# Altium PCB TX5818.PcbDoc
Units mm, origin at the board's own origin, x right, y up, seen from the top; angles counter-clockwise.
Board outline 55.26 x 55.25 mm, 2 copper layers (TopLayer, BottomLayer); 37 components, 34 nets, 107 pads, 481 vias.
Unrouted connection lines stored in the file: 3.
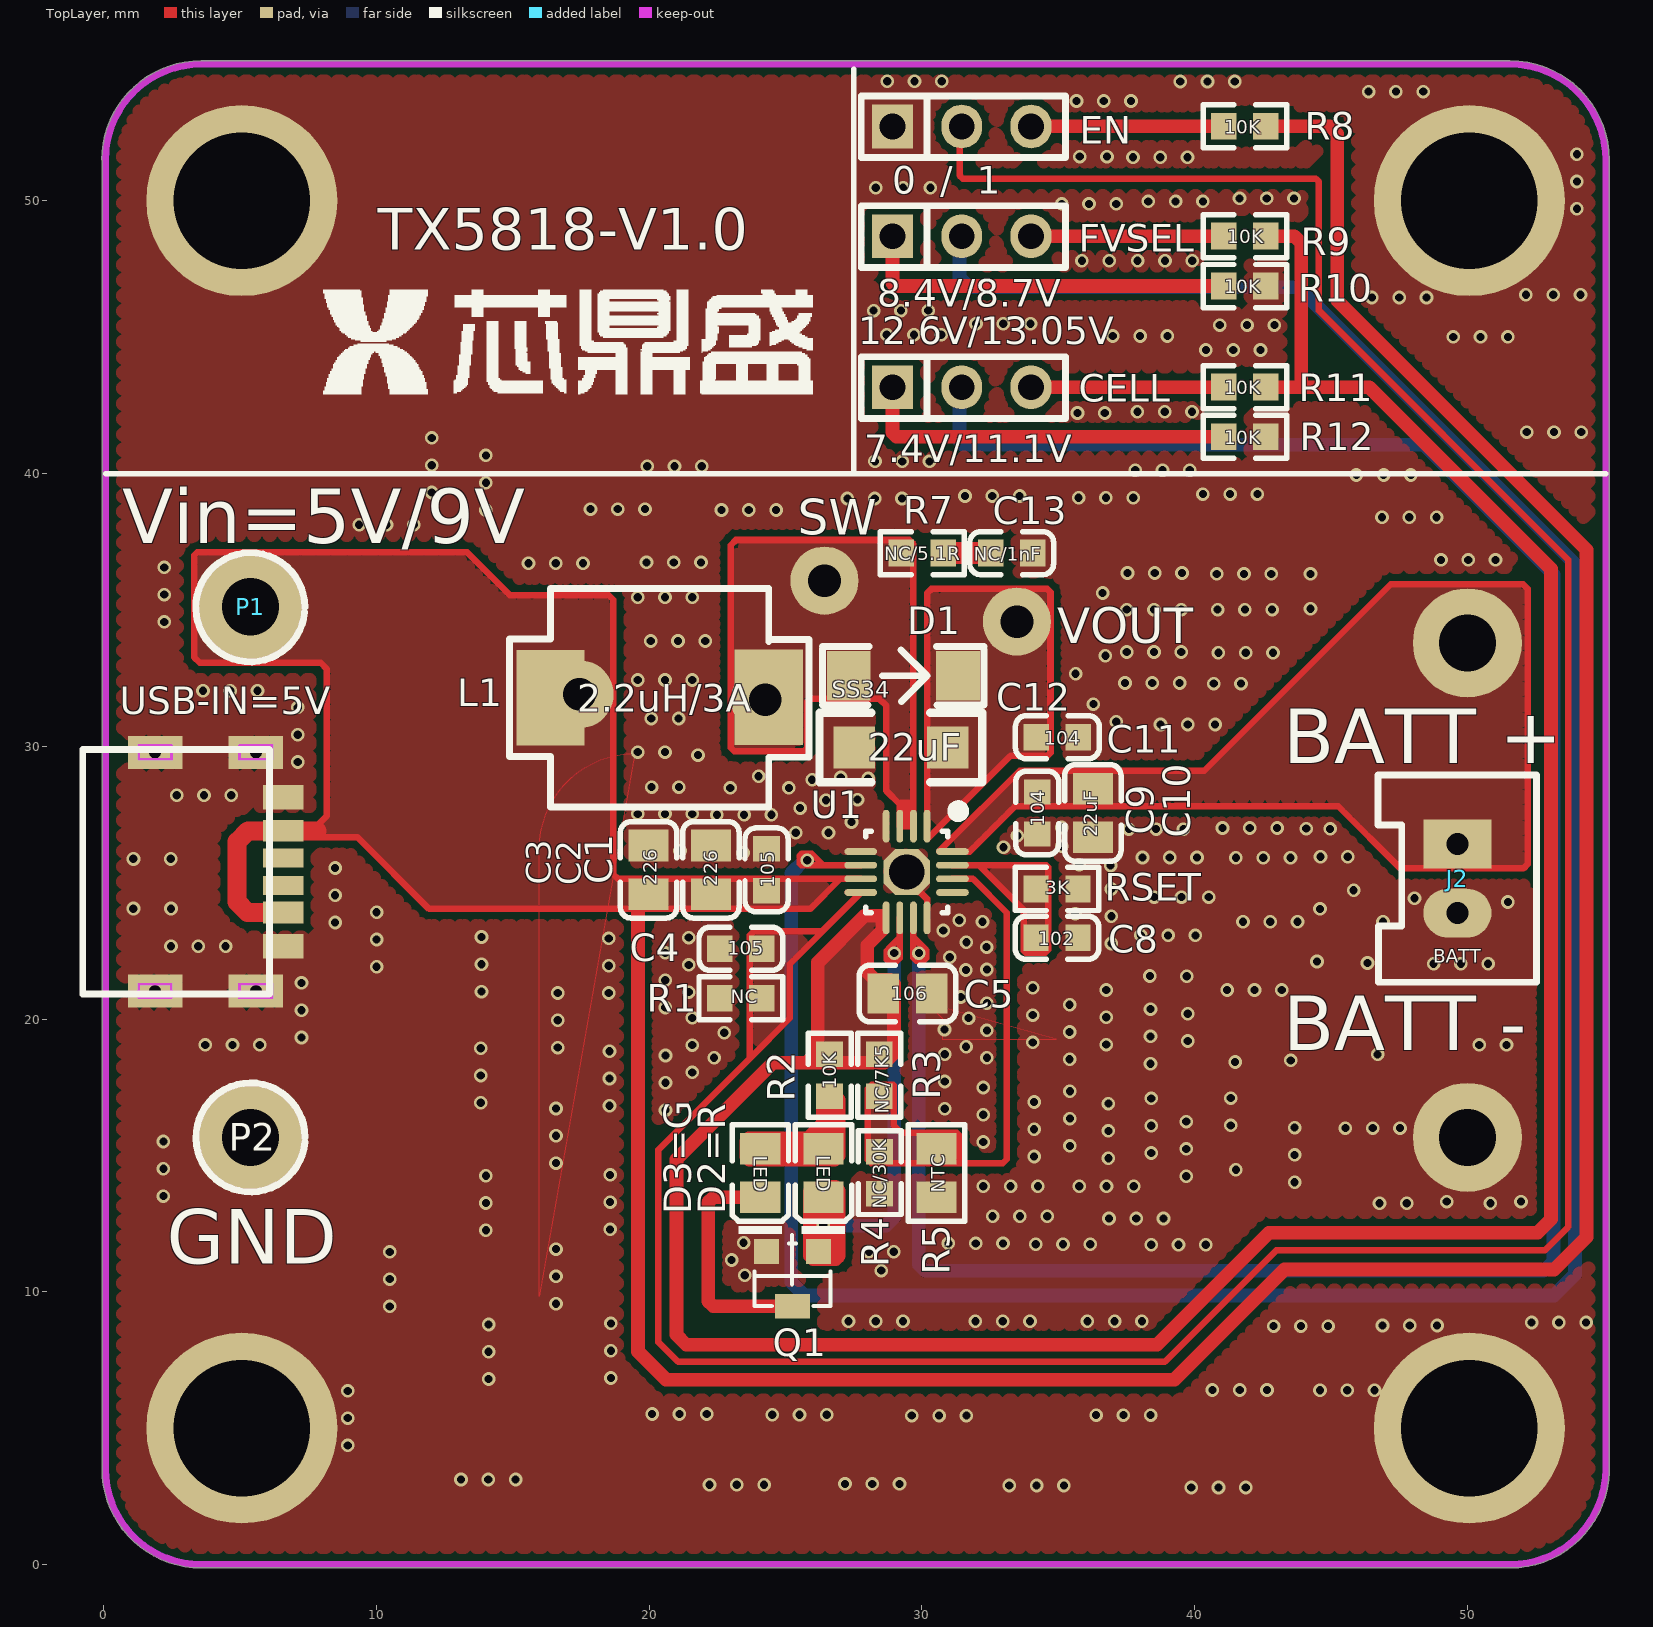
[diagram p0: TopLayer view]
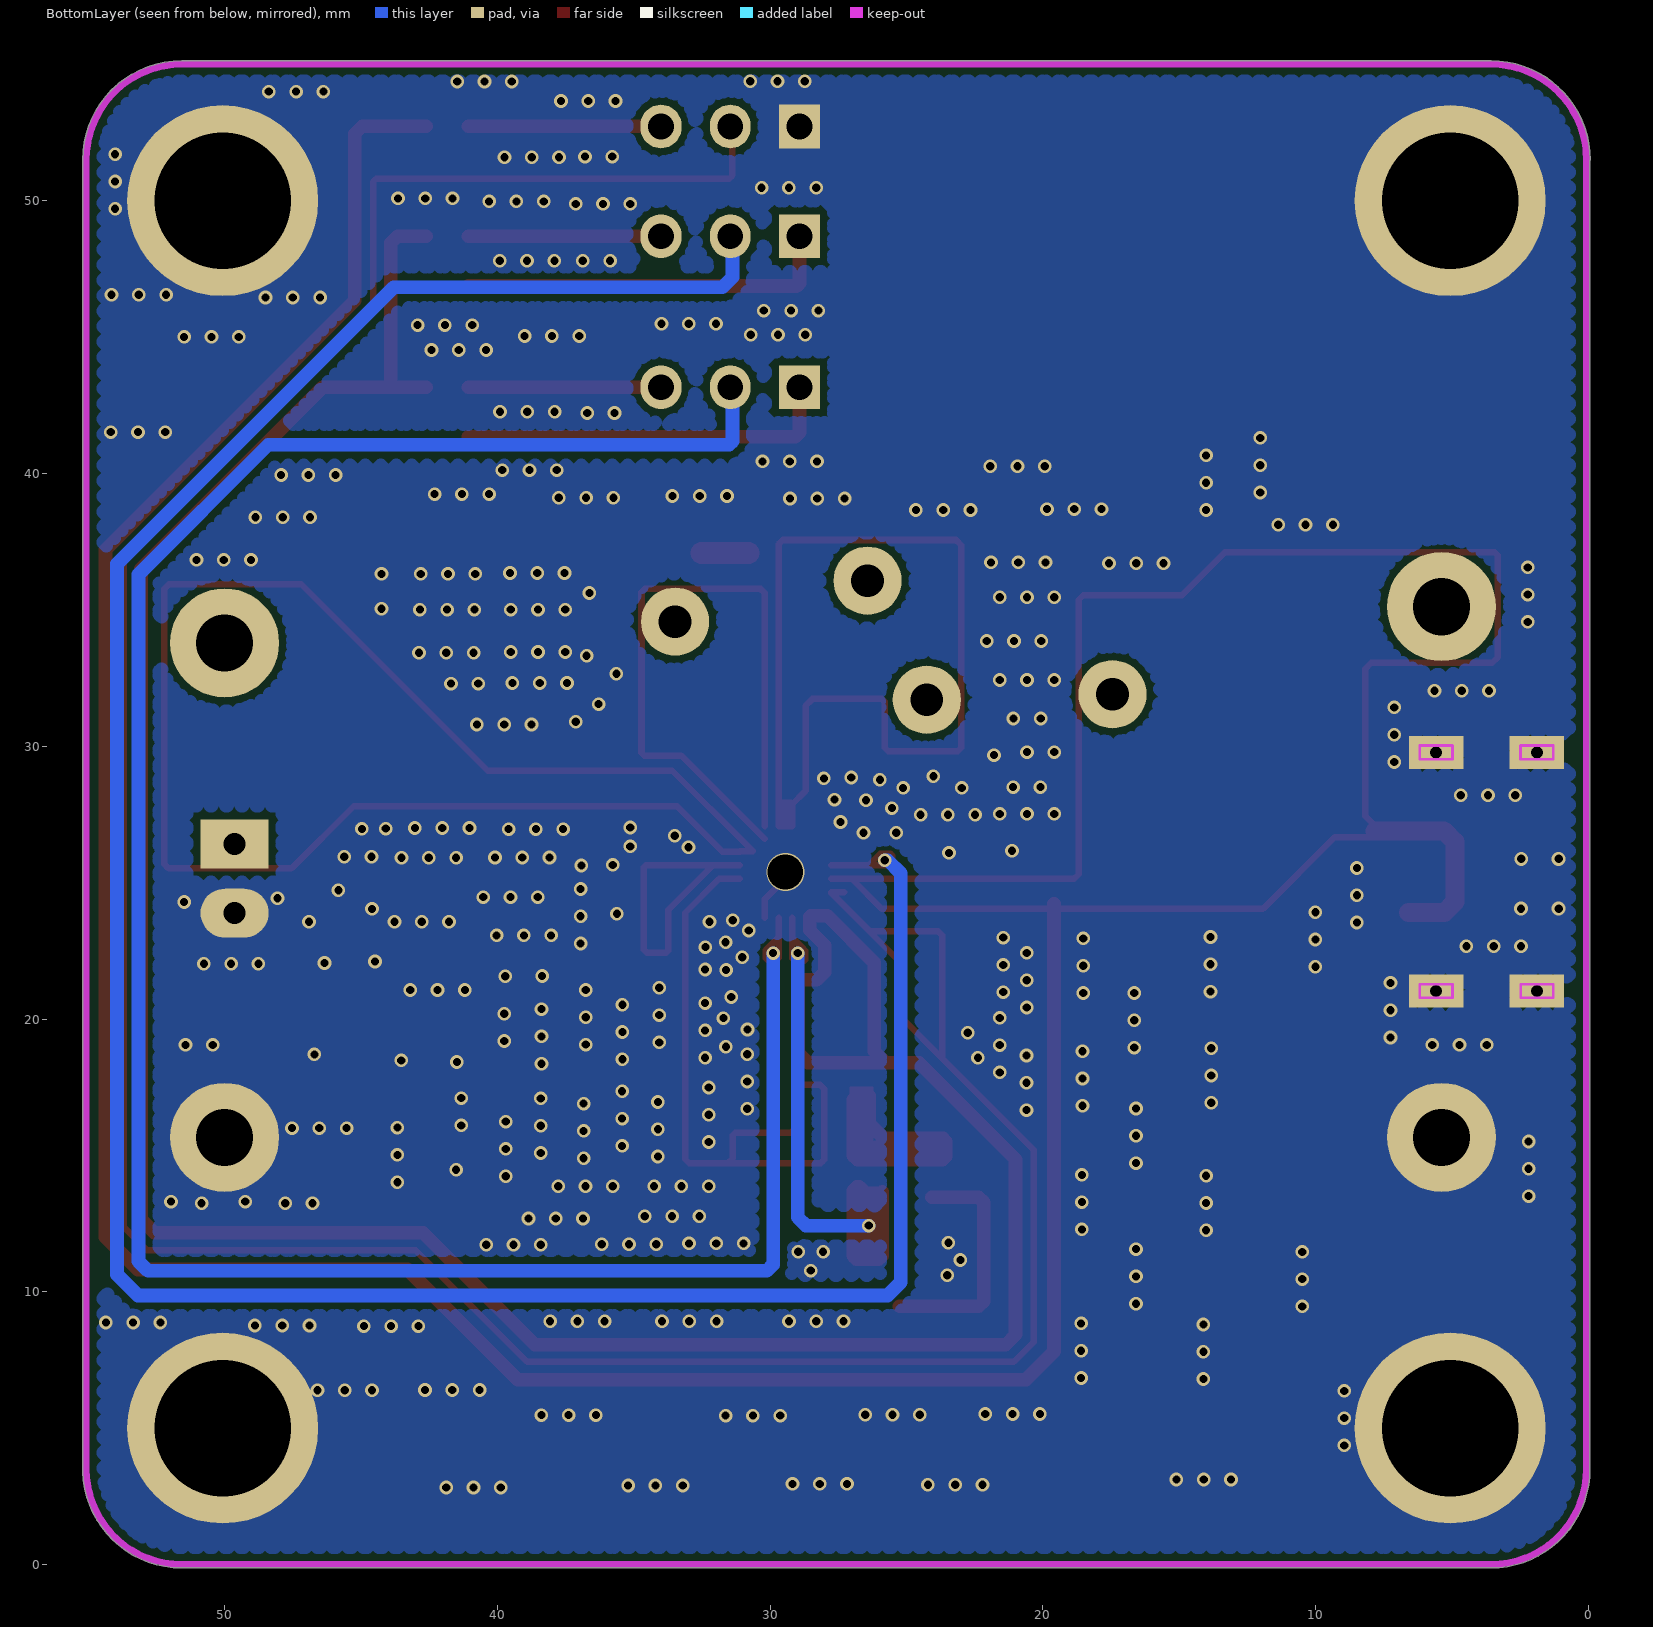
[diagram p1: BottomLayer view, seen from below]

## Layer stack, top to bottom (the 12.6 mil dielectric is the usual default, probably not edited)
TopLayer: signal copper 0.0356
Dielectric: dielectric 0.32, FR-4, Dk 4.8
BottomLayer: signal copper 0.0356

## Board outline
-0.057,3.51 -0.057,46.299 cw(c0.07,46.306) -0.057,46.306 -0.057,51.479 cw(c0.066,51.51) -0.061,51.51 cw(c3.566,51.51) 3.566,55.137 cw(c3.566,55.01) 3.567,55.137 51.572,55.137 cw(c51.572,51.51) 55.199,51.51 cw(c55.072,51.51) 55.199,51.51 55.198,3.527 cw(c55.072,3.51) 55.199,3.51 cw(c51.572,3.51) 55.198,3.416 55.198,3.414 cw(c55.07,3.414) 55.197,3.405 cw(c51.572,3.51) 51.572,-0.118 3.57,-0.118 cw(c3.57,3.51)

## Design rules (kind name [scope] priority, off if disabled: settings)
Clearance [All] p1: gap=0.254
PolygonConnect [All] p1: connectstyle=Direct reliefconductorwidth=0.254 reliefentries=4 polygonreliefangle="90 Angle"
RoutingVias [All] p1: holewidth=0.381 width=0.432 viastyle="Through Hole" minholewidth=0.381 minwidth=0.432 maxholewidth=0.381 maxwidth=0.432
SilkscreenOverComponentPads SilkToSolderMaskClearance [IsPad] p1: minsilkscreentomaskgap=0.254
SolderMaskExpansion [All] p1: expansion=0.102
TestPointUsage [All] p1: valid=0 allowmultiple=FALSE
Testpoint [All] p1: side=3 testpointundercomponent=TRUE minsize=1.016 maxsize=2.54 preferedsize=1.524 minholesize=0.508 maxholesize=1.016 preferedholesize=0.813 testpointgrid=0.025 style=297 order=0-112345678
Width [All] p1: maxlimit=5.08 minlimit=0.15 preferedwidth=0.24
23 further rules are at their usual default settings.

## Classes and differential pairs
component class NS4296_DEMO_V1: C2 C8 C12 C18 C34 C37 C38 C39 C40 J3 J4 J5 J6 J7 J9 J10 LS1 LS2 LS3 R4 R6 R10 RSET S2 S3 USB-IN=5V
component class PA: C12 C15 C16 C17 C18 C19 C20 C26 C34 C35 C36 C40 C62 C66 Cc Ci+ Ci- Cp J9 Jin LS3 R0/nc R6 R8 R19 R46 Rc2 Rf Rg Ro- U3 U8 U9 Uic
component class NS4358_2: C12 C15 C16 C17 C18 C19 C20 C26 C30 C34 C35 C36 C40 Cc Cg Ci+ Ci- Cp J5 J9 Jin Jp LS3 R0/nc R6 R8 R19 Rc2 Rf Rg Ro- Uic
component class NS4158_DEMO: C2 Cb Cc Cg Ci+ Ci- Cp Cv Jin Jp LSo R0/nc Rc1 Rc2 Rf Rg Ri+ Ri- Sc Uic Xi Xig Xo+ Xo- Xv+ Xv-
component class ANT2801DEMO_160412: C2 C12 D1 D2=R IC1 J2 L1 P1 P2 R6 R10 RSET S1 USB-IN=5V

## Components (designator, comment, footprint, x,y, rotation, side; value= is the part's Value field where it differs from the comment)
C1 "105" LC-0603_C 24.304,25.475 r90 top
C2 "226" LC-0805_C 22.262,25.475 r90 top
C3 "226" LC-0805_C 19.98,25.475 r90 top
C4 "105" LC-0603_C 23.363,22.583 r0 top
C5 "106" LC-0805_C 29.469,20.941 r180 top
C8 "102" LC-0603_C 34.955,22.983 r180 top
C9 "104" LC-0603_C 34.224,27.557 r90 top
C10 "22uF" LC-0805_C 36.266,27.557 r90 top
C11 "104" LC-0603_C 34.965,30.34 r0 top
C12 "22uF" 1206 27.517,29.96 r0 top
C13 "NC/1nF" LC-0603_C 33.293,37.087 r180 top
CELL "7.4V/11.1V" SIP-3_2.54 28.9,43.173 r0 top
D1 "SS34" D0-214 27.307,32.593 r0 top
D2=R "LED" LC-0805_LED_S1 26.386,14.364 r90 top
D3=G "LED" LC-0805_LED_S1 24.074,14.364 r90 top
EN "0  /  1" SIP-3_2.54 28.9,52.733 r0 top
FVSEL "8.4V/8.7V" SIP-3_2.54 28.9,48.709 r0 top
J2 "BATT" SIP2 49.63,26.426 r270 top
L1 "2.2uH/3A" L5 16.386,31.782 r0 top
P1 "5V" JG1.0#1 4.004,33.794 r0 top
P2 "PGND" JG1.0#2 4.004,15.876 r0 top
Q1 "2302" SOT-23 26.216,11.501 r180 top
R1 "NC" LC-0603_R 23.363,20.771 r0 top
R2 "10K" LC-0603_R 26.617,17.948 r270 top
R3 "NC/7K5" LC-0603_R 28.438,17.948 r270 top
R4 "NC/30K" LC-0603_R 28.448,14.374 r270 top
R5 "NTC" 0805_L 30.531,14.364 r90 top
R7 "NC/5.1R" LC-0603_R 30.01,37.087 r180 top
R8 "10K" LC-0603_R 41.842,52.733 r180 top
R9 "10K" LC-0603_R 41.842,48.709 r180 top
R10 "10K" LC-0603_R 41.842,46.877 r180 top
R11 "10K" LC-0603_R 41.842,43.173 r180 top
R12 "10K" LC-0603_R 41.842,41.351 r180 top
RSET "3K" LC-0603_R 34.955,24.775 r180 top
TX5818-V1.0 "Comment" LOGO(18x4)mm 15.786,44.014 r0 top
U1 "TX5818" QFN-3X3-16L 29.439,25.395 r180 top
USB-IN=5V "Comment" USB-TYPE_C_6P_W 6.086,25.405 r270 top

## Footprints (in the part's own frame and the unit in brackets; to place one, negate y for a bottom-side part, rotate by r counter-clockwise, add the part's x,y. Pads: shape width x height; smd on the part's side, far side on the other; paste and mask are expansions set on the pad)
0805_L [mm]
  rect 1.16x1.47 smd: 1(-0.892,0) 2(0.888,0)
  silkscreen extent -1.77,-1.04 1.77,1.03
1206 [mil]
  rect 60x60 smd: 1(0,0) 2(135,0)
  silkscreen extent -50,-50 185,50
D0-214 [mm]
  rect 1.6x1.8 smd: 1(0.014,-0.002) 2(4.014,-0.002)
  silkscreen extent -0.96,-1.07 4.97,1.07
JG1.0#1 [mm]
  round 4 hole 2.1: 1(1.381,1.331)
  silkscreen extent -0.62,-0.69 3.38,3.31
JG1.0#2 [mm]
  round 4 hole 2.1: 1(1.381,-0.21)
  silkscreen extent -0.62,-2.21 3.38,1.79
L5 [mm]
  rect 2.5x3.5 smd: 1(0,0) 2(8,0.025)
  silkscreen extent -1.5,-4 9.47,4
LC-0603_C [mm]
  rect 0.93x0.98 smd: 1(-0.77,0) 2(0.77,0)
  silkscreen extent -1.53,-0.79 1.54,0.79
LC-0603_R [mm]
  rect 0.93x0.98 smd: 1(-0.77,0) 2(0.77,0)
  silkscreen extent -1.53,-0.79 1.54,0.79
LC-0805_C [mm]
  rect 1.16x1.47 smd: 1(-0.89,0) 2(0.89,0)
  silkscreen extent -1.77,-1.03 1.77,1.04
LC-0805_LED_S1 [mm]
  rect 1.16x1.47 smd: A(0.89,0) K(-0.89,0)
  silkscreen extent -2.25,-1.04 1.77,1.03
LOGO(18x4)mm [mm]
  silkscreen extent -7.73,-1.09 10.22,2.72
QFN-3X3-16L [mm]
  oval 0.25x1.2 smd: 1(-0.75,-1.68) 2(-0.25,-1.68) 3(0.25,-1.68) 4(0.75,-1.68) 9(0.75,1.68) 10(0.25,1.68) 11(-0.25,1.68) 12(-0.75,1.68)
  oval 1.2x0.25 smd: 5(1.68,-0.75) 6(1.68,-0.25) 7(1.68,0.25) 8(1.68,0.75) 13(-1.68,0.75) 14(-1.68,0.25) 15(-1.68,-0.25) 16(-1.68,-0.75)
  oct 1.7x1.7 smd: 17(0,0)
  silkscreen extent -2.09,-2.43 1.5,1.5
SIP2 [mm]
  rect 1.8x2.5 hole 0.813: 1(-0.001,0.002)
  oval 1.8x2.5 hole 0.813: 2(2.539,0.002)
  silkscreen extent -2.53,-2.91 5.07,2.9
SIP-3_2.54 [mm]
  rect 1.5x1.6 hole 0.95: 1(0.02,-0.006)
  oval 1.5x1.6 hole 0.95: 2(2.56,-0.006) 3(5.1,-0.006)
  silkscreen extent -1.12,-1.15 6.37,1.11
SOT-23 [mil]
  rect 36x36 smd: B(0.24,0.43) E(75.24,0.43)
  rect 50x36 smd: C(37.74,79.79)
  silkscreen extent -17,-23 93,79
USB-TYPE_C_6P_W [mm]
  rect 1.2x2 hole 0.45: 1(-4.375,-0.5) 1(-4.375,-4.2) 1(4.375,-0.5) 1(4.375,-4.2)
  rect 0.9x1.5 smd: 1(-2.73,0.5) 6(2.73,0.5)
  rect 0.8x1.5 smd: 2(-1.5,0.5) 5(1.5,0.5)
  rect 0.7x1.5 smd: 3(-0.5,0.5) 4(0.5,0.5)
  KeepOutLayer lines w0.1: 4.624,-4.801 4.124,-4.801 4.124,-3.601 4.624,-3.601 4.624,-4.801 ; -4.127,-4.8 -4.627,-4.8 -4.627,-3.6 -4.127,-3.6 -4.127,-4.8 ; 4.621,-1.1 4.121,-1.1 4.121,0.1 4.621,0.1 4.621,-1.1 ; -4.126,-1.1 -4.626,-1.1 -4.626,0.1 -4.126,0.1 -4.126,-1.1
  silkscreen extent -4.47,-6.85 4.47,0

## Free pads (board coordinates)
  round 7 hole 5: 0(5.07,5.01) 0(5.07,50.01) 0(50.072,5.01) 0(50.072,50.01)
  round 4 hole 2.1: 0(50,33.794) 1(50,15.666)
  round 2.5 hole 1.2: 2(17.447,31.912) 2(24.254,31.712) 2(26.426,36.076) 3(33.483,34.575)

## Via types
v1: diameter 0.5, hole 0.3, TopLayer to BottomLayer, 476 vias
v2: diameter 0.508, hole 0.305, TopLayer to BottomLayer, 4 vias
v3: diameter 1.4, hole 1.3, TopLayer to BottomLayer, 1 vias

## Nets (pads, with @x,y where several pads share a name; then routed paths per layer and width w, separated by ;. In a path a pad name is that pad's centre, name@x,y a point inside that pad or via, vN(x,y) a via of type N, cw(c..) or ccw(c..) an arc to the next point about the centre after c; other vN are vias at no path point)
5V: 
AGND: 
BATT: C9.2 C10.2 J2.1 pad.0@50,33.794 U1.16 | length 59.1
  TopLayer w0.24: U1.16@30.631,26.156 31.109,26.156 U1.16 31.751,26.145 33.413,27.808 34.224,27.808 36.266,27.808 45.265,27.808 47.547,25.525 49.632,25.525 52.052,25.525 52.212,25.686 52.212,35.776 52.042,35.946 47.187,35.946 40.35,29.109 36.266,29.109 33.584,29.109 30.87,26.395 U1.16@30.631,26.156
CC1: USB-IN=5V.3
CC2: USB-IN=5V.4
CELL: CELL.2 CELL.3 R11.2 U1.11 | length 95.9
  TopLayer w0.24: U1.11 29.689,22.993 ; 29.689,22.993 29.689,22.423 29.689,22.252 29.704,22.237 29.79,22.152 29.889,22.152 30.07,22.152 30.115,22.197 30.15,22.232 30.15,22.423 30.15,22.533 30.075,22.608 29.689,22.993
  TopLayer w0.5: CELL.3@34,43.173 R11.2
  BottomLayer w0.5: v1(29.889,22.423) 29.889,11.001 30.12,10.771 52.803,10.771 53.153,11.121 53.153,36.306 48.398,41.061 31.501,41.061 31.38,41.182 31.38,43.167 CELL.2@31.38,43.18
COMP: 
EN: C4.2 EN.2 EN.3 R1.2 R8.2 U1.8 | length 129.4
  TopLayer w0.24: 23.577,18.451 23.694,18.568 ; U1.8@27.278,24.645 U1.8 ; EN.2@31.38,52.739 31.38,52.727 31.38,50.932 31.501,50.811 44.444,50.811 44.555,50.701 44.555,45.976 53.694,36.837 53.694,12.382 52.833,11.522 42.993,11.522 38.909,7.437 21.061,7.437 20.34,8.158 20.34,15.215 23.694,18.569 ; 23.694,18.569 25.155,20.03 25.155,22.012 27.759,24.616 U1.8 ; 23.694,18.569 23.694,20.771 23.694,22.583 23.694,23.073 23.844,23.223 26.337,23.223 U1.8
  TopLayer w0.5: EN.3@34,52.739 R8.2@41.065,52.739
FVSEL: FVSEL.2 FVSEL.3 R9.2 U1.6 | length 110.2
  TopLayer w0.24: U1.6 26.376,25.645 ; 26.376,25.645 25.796,25.645 25.576,25.645 25.525,25.696 25.525,25.826 25.525,25.996 25.576,26.046 25.586,26.056 25.796,26.056 25.966,26.056 25.996,26.026 26.376,25.645
  TopLayer w0.5: FVSEL.3@34,48.709 R9.2
  BottomLayer w0.5: v1(25.796,25.826) 25.686,25.826 25.205,25.345 25.205,10.36 25.696,9.87 53.173,9.87 53.944,10.641 53.944,36.687 43.804,46.827 31.752,46.827 31.38,47.198 31.38,48.703 FVSEL.2@31.38,48.715
ISET: C8.2 RSET.2 U1.15 | length 11.4
  TopLayer w0.24: U1.15 32.092,25.645 ; 32.092,25.645 34.555,25.645 34.635,25.566 34.635,24.775 34.635,22.983 34.635,22.553 34.625,22.543 34.518,22.436 34.185,22.436 33.81,22.436 33.734,22.512 33.734,22.983 33.734,24.004 32.092,25.645
LDO: C5.2 R2.1 R3.1 R9.1 R11.1 U1.9 | length 106.8
  TopLayer w0.5: R11.1 43.904,43.173 ; R9.1 43.654,48.709 43.904,48.458 43.904,43.173 ; 25.766,18.398 26.186,18.819 26.186,22.082 27.898,23.794 28.508,23.794 28.549,23.754 28.549,23.715 28.549,23.263 27.998,22.713 27.998,21.732 28.288,21.441 28.579,21.441 28.829,21.441 28.954,21.316 28.979,21.291 28.979,20.941 28.979,18.759 28.688,18.468 28.619,18.398 28.438,18.398 26.617,18.398 25.766,18.398 ; 25.766,18.398 24.535,18.398 21.001,14.865 21.001,8.428 21.361,8.068 38.619,8.068 42.723,12.172 52.573,12.172 53.063,12.663 53.063,36.506 46.396,43.173 43.904,43.173
LED: D2=R.K Q1.B U1.10 | length 22.2
  TopLayer w0.24: U1.10 29.189,22.993 ; 29.189,22.993 29.189,22.423 29.189,22.242 29.179,22.232 29.089,22.142 28.989,22.142 28.749,22.142 28.729,22.162 28.709,22.182 28.709,22.423 28.709,22.512 28.804,22.608 29.189,22.993
  TopLayer w0.5: D2=R.K@25.886,13.674 25.886,13.474 25.886,11.491 25.886,11.331 25.968,11.249 26.016,11.201 26.21,11.201 26.837,11.201 26.957,11.321 26.957,13.474 26.957,13.714 26.817,13.854 26.727,13.854 26.386,13.514 D2=R.K
  BottomLayer w0.5: v1(26.386,12.432) 28.689,12.432 28.989,12.733 v1(28.989,22.423)
NetC6_1: D3=G.K Q1.C | length 8.8
  TopLayer w0.5: D3=G.K 22.353,13.474 22.162,13.283 22.162,9.66 22.347,9.475 Q1.C
NetC11_2: 
NetIC1_1: 
NetIC1_4: 
NetIC1_17: 
NetIC1_20: 
NetL1_1: 
NetR2_2: 
NetR3_2: 
NetR4_2: 
NetR6_1: 
NetR7_2: C13.2 R7.1 | length 1.7
  TopLayer w0.8: R7.1 C13.2
NetR9_2: D2=R.A D3=G.A R2.2 | length 10.6
  TopLayer w0.5: R2.2@26.376,17.187 26.376,16.176 25.826,15.626 23.664,15.626 23.564,15.526 23.564,14.955 23.674,14.845 26.807,14.845 26.957,14.995 26.957,17.047 26.826,17.178 R2.2
NetR10_2: FVSEL.1 R10.2 | length 13.9
  TopLayer w0.5: FVSEL.1 28.92,46.976 29.019,46.877 R10.2
NetR12_2: CELL.1 R12.2 | length 13.9
  TopLayer w0.5: CELL.1 28.92,41.5 29.069,41.351 R12.2
NetS1_1: 
NTC: R3.2 R4.1 R5.2 U1.14 | length 25.5
  TopLayer w0.24: U1.14 31.872,25.145 33.113,23.904 33.113,14.865 32.963,14.715 31.562,14.715 ; 31.562,14.715 30.531,14.715 28.448,14.715 28.148,14.715 28.083,14.779 28.018,14.845 28.018,15.144 28.018,17.178 28.018,17.447 28.093,17.523 28.168,17.598 28.438,17.598 28.949,17.598 28.969,17.578 28.969,17.178 28.969,16.106 29.239,15.836 30.531,15.836 31.281,15.836 31.371,15.746 31.371,15.252 31.371,14.905 31.562,14.715
PGND: C1.2 C2.2 C3.2 C4.1 C5.1 C8.1 C9.1 C10.1 C11.2 C12.1 C13.1 EN.1 J2.2 P2.1 pad.0@5.07,5.01 pad.0@5.07,50.01 pad.0@50.072,5.01 pad.0@50.072,50.01 pad.1 Q1.E R1.1 R4.2 R5.1 R10.1 R12.1 RSET.1 U1.4 U1.5 U1.12 U1.17 USB-IN=5V.1 USB-IN=5V.6 | length 2
  TopLayer w0.24: v3(29.439,25.395) 29.439,25.155 30.189,24.405 U1.12
  other v1: 39.872,2.833 40.872,2.833 41.872,2.833 33.205,2.903 34.205,2.903 35.205,2.903 22.214,2.933 23.214,2.933 24.214,2.933 27.179,2.963 28.179,2.963 29.179,2.963 13.105,3.123 14.105,3.123 15.105,3.123 8.949,4.374 8.949,5.374 29.63,5.465 30.63,5.465 31.63,5.465 24.514,5.495 25.514,5.495 26.514,5.495 36.386,5.485 37.386,5.485 38.386,5.485 20.11,5.526 21.11,5.526 22.11,5.526 8.949,6.374 40.651,6.406 41.651,6.406 42.651,6.406 44.595,6.396 45.595,6.396 46.595,6.396 14.114,6.807 18.599,6.847 14.114,7.807 18.599,7.847 42.893,8.749 43.893,8.749 44.893,8.749 46.887,8.769 47.887,8.769 48.887,8.769 14.114,8.807 18.599,8.847 52.352,8.879 53.352,8.879 54.352,8.879 27.307,8.929 28.307,8.929 29.307,8.929 31.962,8.929 32.962,8.929 33.962,8.929 36.066,8.929 37.066,8.929 38.066,8.929 10.49,9.469 16.587,9.57 10.49,10.469 16.587,10.57 23.503,10.611 28.508,10.781 23.023,11.171 10.49,11.469 28.058,11.471 28.969,11.471 16.587,11.57 34.174,11.752 35.174,11.752 36.174,11.752 38.408,11.732 39.408,11.732 40.408,11.732 23.463,11.802 30.971,11.782 31.971,11.782 32.971,11.782 14.014,12.262 18.569,12.292 36.857,12.693 37.857,12.693 38.857,12.693 32.593,12.773 33.593,12.773 34.593,12.773 14.014,13.262 46.776,13.253 47.776,13.253 50.841,13.253 18.569,13.292 49.239,13.313 51.962,13.313 2.192,13.514 32.252,13.874 33.252,13.874 34.252,13.874 35.766,13.874 36.766,13.874 37.766,13.874 43.664,14.024 14.014,14.262 39.69,14.244 18.569,14.292 41.511,14.482 2.192,14.514 16.587,14.725 36.837,14.905 34.114,14.965 43.664,15.024 38.408,15.095 39.69,15.244 35.425,15.355 32.252,15.495 2.192,15.514 16.587,15.725 36.837,15.905 34.114,15.965 45.525,16.006 46.525,16.006 47.525,16.006 43.664,16.024 38.408,16.095 41.321,16.106 39.69,16.244 35.425,16.355 32.252,16.495 20.601,16.667 16.587,16.725 30.841,16.717 18.549,16.827 36.837,16.905 13.824,16.937 34.114,16.965 38.408,17.095 41.321,17.106 35.425,17.355 32.252,17.495 20.601,17.667 30.841,17.717 18.549,17.827 13.824,17.937 21.582,18.048 38.378,18.368 41.481,18.428 43.523,18.488 35.415,18.529 22.382,18.589 32.382,18.589 20.601,18.667 46.707,18.709 30.841,18.717 18.549,18.827 13.824,18.937 16.647,18.959 31.622,18.989 3.724,19.059 4.724,19.059 5.724,19.059 21.582,19.048 50.43,19.059 51.43,19.059 36.757,19.069 34.064,19.149 39.75,19.199 7.257,19.329 38.378,19.368 22.753,19.499 35.415,19.529 32.382,19.589 30.831,19.62 16.647,19.959 21.582,20.048 31.712,20.04 36.757,20.069 34.064,20.149 39.75,20.199 7.257,20.329 38.378,20.368 20.591,20.43 35.415,20.529 32.382,20.589 31.421,20.811 16.647,20.959 18.518,20.961 21.451,20.991 13.854,21.011 36.757,21.069 41.191,21.071 42.191,21.071 43.191,21.071 34.064,21.149 7.257,21.329 20.591,21.43 38.358,21.582 39.71,21.572 31.612,21.802 32.382,21.822 10.01,21.922 18.518,21.961 13.854,22.011 21.451,21.991 48.759,22.032 49.759,22.032 50.759,22.032 46.336,22.062 44.484,22.112 31.021,22.272 20.591,22.43 32.372,22.643 2.472,22.673 3.472,22.673 4.472,22.673 36.947,22.773 31.632,22.823 10.01,22.922 18.518,22.961 21.451,22.991 13.854,23.011 38.028,23.073 39.028,23.073 40.028,23.073 30.781,23.253 8.488,23.544 32.222,23.574 41.772,23.574 42.772,23.574 43.772,23.574 46.906,23.574 31.371,23.624 36.947,23.773 35.616,23.864 10.01,23.922 44.595,24.044 51.481,24.294 48.058,24.434 38.518,24.474 39.518,24.474 40.518,24.474 8.488,24.544 45.826,24.725 36.947,24.773 8.488,25.544 36.917,25.636 35.766,25.656 38.088,25.926 39.088,25.926 40.088,25.926 41.511,25.916 42.511,25.916 43.511,25.916 44.615,25.956 45.615,25.956 23.443,26.096 21.131,26.176 32.993,26.306 35.125,26.336 33.493,26.727 25.375,26.837 26.577,26.837 37.588,26.967 38.588,26.967 39.588,26.967 44.094,26.987 44.965,26.977 41.021,27.007 42.021,27.007 43.021,27.007 35.125,27.027 27.417,27.227 22.482,27.497 23.482,27.497 24.482,27.497 19.58,27.527 20.58,27.527 21.58,27.527 25.536,27.738 26.486,28.028 27.638,28.048 2.683,28.208 3.683,28.208 4.683,28.208 22.973,28.478 25.123,28.478 20.09,28.508 21.09,28.508 25.976,28.779 28.028,28.829 27.027,28.859 24.014,28.909 7.117,29.429 21.792,29.68 19.58,29.79 20.58,29.79 7.117,30.429 38.749,30.801 39.749,30.801 40.749,30.801 37.127,30.901 20.08,31.021 21.08,31.021 7.117,31.429 36.286,31.552 3.644,32.042 4.644,32.042 5.644,32.042 37.447,32.322 38.447,32.322 39.447,32.322 40.701,32.302 41.701,32.302 19.58,32.432 20.58,32.432 21.58,32.432 35.636,32.663 36.727,33.323 40.871,33.433 41.871,33.433 42.871,33.433 37.507,33.463 38.507,33.463 39.507,33.463 20.06,33.864 21.06,33.864 22.06,33.864 2.222,34.565 37.507,35.015 38.507,35.015 39.507,35.015 40.841,35.015 41.841,35.015 42.841,35.015 44.244,35.045 19.58,35.465 20.58,35.465 21.58,35.465 2.222,35.565 36.627,35.626 40.811,36.326 41.811,36.326 42.811,36.326 44.244,36.326 37.537,36.356 38.537,36.356 39.538,36.356 2.222,36.565 15.578,36.717 16.578,36.717 17.578,36.717 19.902,36.747 20.902,36.747 21.902,36.747 49.031,36.837 50.031,36.837 51.031,36.837 9.369,38.128 10.369,38.128 11.369,38.128 46.869,38.398 47.869,38.398 48.869,38.398 14.014,38.669 22.655,38.669 23.655,38.669 24.655,38.669 17.85,38.699 18.85,38.699 19.85,38.699 27.269,39.089 28.269,39.089 29.269,39.089 35.746,39.119 36.746,39.119 37.746,39.119 31.582,39.179 32.582,39.179 33.582,39.179 40.3,39.249 41.3,39.249 42.3,39.249 12.032,39.309 14.014,39.669 45.928,39.95 46.928,39.95 47.928,39.95 37.82,40.13 38.82,40.13 39.82,40.13 19.932,40.27 20.932,40.27 21.932,40.27 12.032,40.309 28.28,40.45 29.28,40.45 30.28,40.45 14.014,40.669 12.032,41.309 52.174,41.521 53.174,41.521 54.174,41.521 35.707,42.222 36.707,42.222 37.9,42.272 38.9,42.272 39.9,42.272 40.412,44.534 41.412,44.534 42.412,44.534 49.481,45.015 50.481,45.015 51.481,45.015 36.999,45.045 37.999,45.045 38.999,45.045 28.711,45.095 29.711,45.095 30.711,45.095 40.923,45.445 41.923,45.445 42.923,45.445 31.984,45.495 32.984,45.495 33.984,45.495 28.23,45.976 29.23,45.976 30.23,45.976 46.498,46.456 47.498,46.456 48.498,46.456 52.144,46.557 53.144,46.557 54.144,46.557 35.867,47.808 36.867,47.808 37.91,47.808 38.91,47.808 39.91,47.808 54.014,49.712 35.127,49.89 36.127,49.89 37.127,49.89 38.3,49.98 39.3,49.98 40.3,49.98 41.644,50.09 42.644,50.09 43.644,50.09 28.31,50.48 29.31,50.48 30.31,50.48 54.014,50.712 37.74,51.602 38.74,51.602 39.74,51.602 35.787,51.622 36.787,51.622 54.014,51.712 35.668,53.664 36.668,53.664 37.668,53.664 46.378,54.004 47.378,54.004 48.378,54.004 28.731,54.384 29.731,54.384 30.731,54.384 39.471,54.374 40.471,54.374 41.471,54.374
  other v2: 1.091,24.054 2.472,24.054 1.091,25.876 2.462,25.876
SW: D1.1 L1.2 pad.2@24.254,31.712 pad.2@26.426,36.076 R7.2 U1.2 U1.3 | length 37.4
  TopLayer w0.24: 22.993,29.95 23.123,29.82 25.666,29.82 25.796,29.95 25.796,31.632 25.906,31.742 27.321,31.742 28.448,31.742 28.699,31.491 28.699,28.368 29.189,27.878 U1.3 U1.2 29.689,37.087 29.689,37.418 29.63,37.477 29.54,37.568 29.24,37.568 23.183,37.568 22.993,37.377 22.993,31.712 22.993,29.95
Vin: C1.1 C2.1 C3.1 L1.1 P1.1 pad.2@17.447,31.912 R8.1 U1.7 USB-IN=5V.2 USB-IN=5V.5 | length 179
  TopLayer w0.24: U1.7 27.007,25.145 ; 27.007,25.145 25.906,24.044 22.262,24.044 19.98,24.044 19.59,24.044 11.932,24.044 9.299,26.677 7.948,26.677 7.818,26.807 7.818,26.905 7.818,27.087 8.188,27.457 8.188,32.833 7.958,33.063 5.385,33.063 3.524,33.063 3.323,33.263 3.323,35.125 3.323,37.007 3.433,37.117 5.385,37.117 13.323,37.117 14.895,35.546 18.518,35.546 18.689,35.375 18.689,31.912 18.689,25.315 18.859,25.145 19.98,25.145 22.262,25.145 24.304,25.145 27.007,25.145
  TopLayer w0.5: C3.1@19.59,24.233 19.59,24.044 19.59,7.818 20.621,6.787 39.259,6.787 43.293,10.821 53.183,10.821 54.364,12.002 54.364,37.207 45.225,46.346 45.225,52.462 44.955,52.733 R8.1
  TopLayer w0.7: USB-IN=5V.5 5.284,23.905 4.895,24.294 4.895,26.506 5.294,26.905 USB-IN=5V.2 7.818,26.905
VOUT: 
VSYS: C11.1 C12.2 D1.2 pad.3 U1.1 | length 24.9
  TopLayer w0.24: U1.1 30.189,29.96 30.189,35.615 30.35,35.776 33.483,35.776 34.595,35.776 34.715,35.656 34.715,34.575 34.715,30.34 34.715,29.77 34.605,29.66 33.253,29.66 30.429,26.836 U1.1@30.2,26.607
pads on no net: U1.13

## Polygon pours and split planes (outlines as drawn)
EN on TopLayer "TopLayer-EN" (hatched 45Degree grid 0.4 track 0.5, remove dead copper, pour order 2): 23.894,22.953 23.894,19.019 24.895,20.02 24.895,22.112 25.876,23.093 24.054,23.093
LDO on TopLayer "TopLayer-LDO" (hatched 45Degree grid 0.4 track 0.5, remove dead copper, pour order 4): 26.416,21.892 26.416,18.669 28.669,18.669 28.669,21.221 27.908,21.221 27.698,21.431 27.698,22.633 28.268,23.203 28.268,23.554 27.958,23.554 26.376,21.972
NTC on TopLayer "TopLayer-NTC" (hatched 45Degree grid 0.4 track 0.5, remove dead copper, pour order 6): 28.278,17.297 28.278,14.905 31.141,14.905 31.141,15.586 29.119,15.586 28.739,15.966 28.739,17.307
PGND on TopLayer "TopLayer-PGND 1" (hatched 90Degree grid 0 track 0.203, remove dead copper, pour order 8): 15.976,9.84 15.976,26.236 cw(c19.479,26.236) 19.479,29.74
NetIC1_20 on TopLayer "TopLayer-NetIC1_20" (hatched 90Degree grid 0 track 0.203, remove dead copper, pour order 10): 30.19,20.581 30.741,20.03 30.741,19.259 34.925,19.259
Vin on TopLayer "TopLayer-Vin" (hatched 45Degree grid 0.4 track 0.5, remove dead copper, pour order 12): 3.483,36.957 3.483,33.303 8.108,33.303 8.519,32.893 8.519,27.548 8.108,27.137 8.108,26.907 9.409,26.907 12.002,24.314 25.846,24.314 26.516,24.985 18.659,24.985 18.428,25.215 18.428,35.265 14.665,35.265 13.113,36.817 3.554,36.817
SW on TopLayer "TopLayer-SW" (hatched 45Degree grid 0.4 track 0.5, remove dead copper, pour order 14): 23.233,37.327 23.233,30.05 25.455,30.05 25.455,31.862 25.596,32.002 28.589,32.002 28.879,31.712 28.879,28.569 29.369,28.078 29.369,37.307 23.373,37.307
ISET on TopLayer "TopLayer-ISET" (hatched 45Degree grid 0.4 track 0.5, remove dead copper, pour order 16): 34.394,25.425 34.394,22.673 34.014,22.673 34.014,24.054 32.573,25.495 34.354,25.495
BATT on TopLayer "TopLayer-BATT" (hatched 45Degree grid 0.4 track 0.5, remove dead copper, pour order 18): 51.952,35.676 51.952,25.746 47.708,25.746 45.345,28.108 33.273,28.108 31.531,26.366 31.141,26.366 33.634,28.859 40.45,28.859 47.247,35.656 51.892,35.656
VSYS on TopLayer "TopLayer-VSYS" (hatched 45Degree grid 0.4 track 0.5, remove dead copper, pour order 20): 30.47,35.505 30.47,27.147 33.243,29.92 34.424,29.92 34.424,35.566 30.51,35.566
PGND on TopLayer "TopLayer-PGND" (hatched 45Degree grid 0.4 track 0.5, remove dead copper, pour order 22): -0.661,55.465 -0.661,-0.561 55.235,-0.561 55.235,55.335 -0.791,55.335
PGND on BottomLayer "BottomLayer-PGND" (hatched 45Degree grid 0.4 track 0.5, remove dead copper, pour order 24): -1.171,55.465 -1.171,-0.3 55.485,-0.3 55.485,55.596 -2.202,55.596

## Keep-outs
KeepOutLayer:
  lines w0.254: 0.066,51.51 cw(c3.566,51.51) 3.566,55.01 51.572,55.01 cw(c51.572,51.51) 55.072,51.51 55.07,3.414 ; 0.07,46.306 0.07,51.511 ; 0.07,46.404 0.07,3.51 ccw(c3.57,3.51) 3.57,0.01 51.572,0.01 ccw(c51.572,3.51) 55.072,3.51

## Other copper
TopLayer:
  rectangle net LED: 25.966,11.211 27.027,13.874
  rectangle net NetR9_2: 26.216,15.205 27.097,17.528
  rectangle net NetR9_2: 23.604,14.795 26.967,15.546
  rectangle net SW: 29.199,26.987 29.73,28.058

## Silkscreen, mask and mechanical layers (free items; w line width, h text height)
TopOverlay:
  lines w0.2: 0.07,40 55.07,40 ; 27.5,40.13 27.5,54.825
  text "12.6V/13.05V" at 27.658,44.745 h1
  text "SW" at 25.445,37.768 h1.3
  text "Vin=5V/9V" at 0.681,37.447 h2
  text "VOUT" at 34.965,33.784 h1.3
  text "BATT +" at 43.243,29.379 h2
  text "BATT -" at 43.243,18.859 h2
  text "GND" at 2.312,11.031 h2
BottomSolder:
  rectangle: 26.707,23.203 46.848,32.723
  rectangle: 30.881,13.524 46.848,23.383

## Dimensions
3.566,55.01 to 3.57,0.01 on TopOverlay
0.07,46.404 to 55.072,51.51 on TopOverlay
